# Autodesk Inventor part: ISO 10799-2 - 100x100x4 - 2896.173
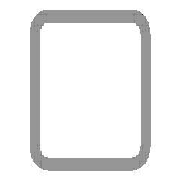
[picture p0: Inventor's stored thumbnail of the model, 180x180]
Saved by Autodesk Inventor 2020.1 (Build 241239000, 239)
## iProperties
Created: 2019-10
Part Number: ISO 10799-2 - 100x100x4 - 2896.173
Material: Stainless Steel
Description: Structural steels - Cold-formed, welded, structural hollow sections
Document SubType Name: Modeling
Standard: ISO
Designer: Synergysoft Dell02
Standard Revision: First edition 2011-09-15
Standards Organization: ISO
Language: en-US
Size Designation: 100x100x4
Categories: <MemberInstance><Categories><Category DisplayName="Structural Shapes" InternalName="089c4875-fa83-4c05-b084-43b9cc11f5ed" Mnemonic="GRDR"><CategoryParameter Dis
Stock Number: 100x100x4
Density: 8 g/cm^3
Appearance: Semi-Polished
_CCFamilyMember: 43
_CCFamilyDisplayName: ISO 10799-2 (Square) - Structural steels - Cold-formed, welded, structural hollow sections
_FrameMemberDoc: Frame Member File
_Version: 15.0.0
_GetPNFromCC: 1
G_L: 2896.173 mm
G_W: 100.000 mm
G_H: 100.000 mm
+B9252E02-7BC7-42CA-962D-DD467EA21C01+CUTDETAIL1: Cut Angle 45.00 deg
+3ECC6B1B-FCED-499B-897D-BBAE757A24CE+CUTDETAIL2: Cut Angle 45.00 deg
+4D97AC9F-0B52-40D7-A5FD-7CF1EC3E7FCC+CUTDETAIL3: Miter 22.50 deg
+FAF08312-805B-409A-AF2E-A7754198D9AC+CUTDETAIL4: Miter 22.50 deg
IsCustomPart: 1
Author: Synergysoft Dell02
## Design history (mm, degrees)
node "Start Plane"
node "End Plane"
sketch "Sketch"
  geometry: L1 (-50, -42)-(-50, 42); L2 (-42, 50)-(42, 50); L3 (50, 42)-(50, -42); L4 (42, -50)-(-42, -50); L5 (-42, 46)-(42, 46); L6 (46, 42)-(46, -42); L7 (42, -46)-(-42, -46); L8 (-46, -42)-(-46, 42); L9 (0, 72.32)-(0, -72.32) reference; L10 (-72.32, 0)-(72.32, 0) reference; A1 r 8 centre (-42, -42) between (-50, -42) and (-42, -50); A2 r 8 centre (42, 42) between (50, 42) and (42, 50); A3 r 8 centre (-42, 42) between (-42, 50) and (-50, 42); A4 r 8 centre (42, -42) between (42, -50) and (50, -42); A5 r 4 centre (-42, 42) between (-42, 46) and (-46, 42); A6 r 4 centre (42, 42) between (46, 42) and (42, 46); A7 r 4 centre (42, -42) between (42, -46) and (46, -42); A8 r 4 centre (-42, -42) between (-46, -42) and (-42, -46)
  constraints: 16 end point, 16 point on circle, 8 centre point, 8 tangent, 4 parallel, 3 equal radius, 2 perpendicular, 7 other
  dimensions: "d7" = 8 radius of A1 (= G_IR); "d9" = 100 distance between parallel lines of L1 L3 (= G_W); "d11" = 100 distance between parallel lines of L2 L4 (= G_H); "d12" = 4 distance between parallel lines of L3 L6 (= G_T); "d15" = 50 distance between parallel lines of L9 L3 (= 0.5 x d9); "d16" = 50 distance between parallel lines of L2 L10 (= 0.5 x d11)
extrude "Body" new body sketch "Sketch" stored distance "d3" = 2896.17317 (= G_L); taper "d4" = 0 deg
node "Driven Length"
  sketch "Sketch3"
    geometry: L1 (0, 0)-(10, 0) reference
    constraints: 2 end point, 1 horizontal
  workplane "Work Plane3"
  sketch "Sketch4"
    geometry: L1 (-2, 51.913)-(12, 51.913) reference; L2 (-2, 2948.087)-(12, 2948.087) reference
    dimensions: "d18" = 2896.17317 distance between parallel lines of L1 L2 (derived)
workplane "Work Plane4"
split "Split1"
workplane "Work Plane5"
split "Split2"
workplane "Work Plane6"
split "Split3"
workplane "Work Plane7"
split "Split4"
body "Solid1"
other parameters: "G_W" = 100 [user parameter; used in 1 equation term], "G_H" = 100 [user parameter; used in 1 equation term], "G_T" = 4 [user parameter; used in 1 equation term], "G_IR" = 8 [user parameter; used in 1 equation term], "G_L" = 2896.17317 (= d18) [user parameter; used in 1 equation term], "G_OFFSET_START" = -51.91342 [user parameter; used in 1 equation term], "G_OFFSET_END" = -51.91342 [user parameter; used in 1 equation term], "d13" = 51.91342 (= -G_OFFSET_START), "d14" = 2948.08658 (= G_OFFSET_END + B_L), "d17" = 90 deg, "MAS" = 1.17 [user parameter]
